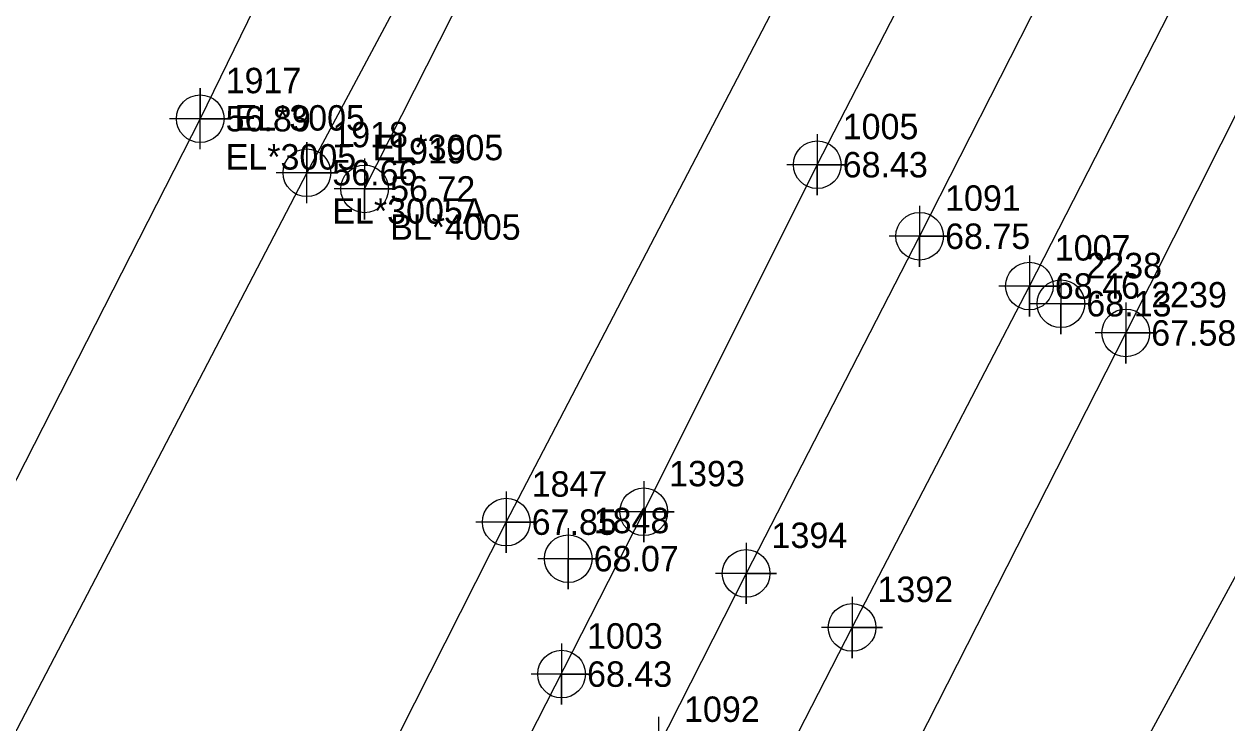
# Model space of a CAD drawing. Extents: x 2062781 to 2066835, y 358981 to 366501.
# Drawn here: x 2065834.6 to 2065952.8, y 365055.9 to 365124.6 of the extents above; entities that cross this region are included whole.
import ezdxf

# ---------------------------------------------------------------- set-up
doc = ezdxf.new("R2010")
doc.units = 0
for name, color, linetype in [('Exist DTM Breakline', 7, 'Continuous'), ('Exist DTM Breakline Cogo Comment', 7, 'Continuous'), ('Exist DTM Breakline Cogo Elevation', 7, 'Continuous'), ('Exist DTM Breakline Cogo Number', 7, 'Continuous'), ('Exist DTM Breakline Cogo Point CELL', 7, 'Continuous'), ('Exist DTM Crownline', 7, 'Continuous'), ('Exist DTM Crownline Cogo Elevation', 7, 'Continuous'), ('Exist DTM Crownline Cogo Number', 7, 'Continuous'), ('Exist DTM Crownline Cogo Point CELL', 7, 'Continuous'), ('Exist DTM Regular Point CELL', 7, 'Continuous'), ('Exist DTM Regular Point Cogo Elevation', 7, 'Continuous'), ('Exist DTM Regular Point Cogo Number', 7, 'Continuous'), ('Exist Roads EOP', 7, 'Continuous'), ('Exist Roads EOP Cogo Elevation', 7, 'Continuous'), ('Exist Roads EOP Cogo Number', 7, 'Continuous'), ('Exist Roads EOP Cogo Point CELL', 7, 'Continuous'), ('Exist Roads Soil', 7, 'Continuous'), ('Exist Roads Soil Cogo Comment', 7, 'Continuous'), ('Exist Roads Soil Cogo Elevation', 7, 'Continuous'), ('Exist Roads Soil Cogo Number', 7, 'Continuous'), ('Exist Roads Soil Cogo Point CELL', 7, 'Continuous')]:
    doc.layers.add(name, color=color, linetype=linetype)

msp = doc.modelspace()

# ---------------------------------------------------------------- linework, layer by layer
at = {"layer": 'Exist DTM Breakline'}
for points in [[(2066391.6, 365972.89), (2066361.73, 365914.52), (2066331.12, 365854.95), (2066302.46, 365802.64), (2066279.52, 365756.79), (2066256.07, 365710.47), (2066233.12, 365662.29), (2066208.82, 365616.84), (2066185.2, 365570.46), (2066159.54, 365522.1), (2066137.86, 365478.97), (2066113.47, 365429.54), (2066089.97, 365381.51), (2066063.32, 365330.49), (2066038.93, 365282.51), (2066014.92, 365234.83), (2065991.3, 365189.77), (2065966.18, 365140.63), (2065942.83, 365094.21), (2065917.49, 365044.37), (2065894.71, 364999.83)], [(2065868.05, 365108.36), (2065887.64, 365147.12), (2065915.95, 365200.53), (2065942.89, 365253.9), (2065967.73, 365303.79), (2065993.42, 365356.29), (2066016.32, 365400.12), (2066036.88, 365439.43), (2066041.92, 365447.71), (2066050.86, 365465.06), (2066067.24, 365500.86), (2066099.12, 365559.9), (2066123.36, 365605.47), (2066146.63, 365650.17), (2066168.17, 365694.53), (2066191.6, 365739.7), (2066213.66, 365782.56), (2066222.79, 365799.42), (2066244.31, 365840.96), (2066263.98, 365879.71), (2066274.73, 365899.77), (2066289.91, 365926.14)], [(2065855.04, 365022.37), (2065881.96, 365075.62), (2065912.8, 365134.88), (2065934.54, 365180.29), (2065958.76, 365228.22), (2065982.22, 365275.67), (2066005.39, 365319.97), (2066028.56, 365365.33), (2066047.41, 365403.57), (2066072.23, 365451.4), (2066094.41, 365496.9), (2066117.74, 365542.01), (2066140.9, 365588.6), (2066164.03, 365634.27), (2066187.25, 365680.45), (2066209.45, 365725.39), (2066232.88, 365773.48), (2066256.9, 365819.9), (2066281.9, 365870.6), (2066303.63, 365917.65)], [(2065937.67, 365040.95), (2065963.89, 365089.22), (2065967.82, 365110.56)]]:
    msp.add_lwpolyline(points, dxfattribs=at)
at = {"layer": 'Exist DTM Breakline Cogo Point CELL'}
for points in [[(2065868.05, 365111.36), (2065868.05, 365105.36), (2065868.05, 365108.36), (2065871.05, 365108.36), (2065865.05, 365108.36)], [(2065942.83, 365097.21), (2065942.83, 365091.21), (2065942.83, 365094.21), (2065945.83, 365094.21), (2065939.83, 365094.21)], [(2065881.96, 365078.62), (2065881.96, 365072.62), (2065881.96, 365075.62), (2065884.96, 365075.62), (2065878.96, 365075.62)]]:
    msp.add_lwpolyline(points, dxfattribs=at)
for centre in [(2065868.05, 365108.36), (2065942.83, 365094.21), (2065881.96, 365075.62)]:
    msp.add_circle(centre, 2.34, dxfattribs=at)
at = {"layer": 'Exist DTM Crownline'}
for points in [[(2066259.93, 365768.45), (2066236.46, 365721.83), (2066212.74, 365674.94), (2066188.43, 365627.04), (2066165.89, 365582.58), (2066140.87, 365533.44), (2066118.2, 365488.77), (2066092.94, 365439.19), (2066070.01, 365393.95), (2066043.74, 365342.11), (2066018.93, 365293.26), (2065993.67, 365243.42), (2065971.81, 365200.42), (2065946.33, 365150.52), (2065922.58, 365103.71), (2065905.53, 365070.58)], [(2065905.53, 365070.58), (2065885.85, 365031.79), (2065868.56, 364997.9), (2065849.54, 364960.7), (2065829.64, 364921.35), (2065809.58, 364881.91), (2065791.06, 364845.43)]]:
    msp.add_lwpolyline(points, dxfattribs=at)
at = {"layer": 'Exist DTM Crownline Cogo Point CELL'}
for points in [[(2065922.58, 365106.71), (2065922.58, 365100.71), (2065922.58, 365103.71), (2065925.58, 365103.71), (2065919.58, 365103.71)], [(2065905.53, 365073.58), (2065905.53, 365067.58), (2065905.53, 365070.58), (2065908.53, 365070.58), (2065902.53, 365070.58)], [(2065905.53, 365073.58), (2065905.53, 365067.58), (2065905.53, 365070.58), (2065908.53, 365070.58), (2065902.53, 365070.58)], [(2065905.53, 365073.58), (2065905.53, 365067.58), (2065905.53, 365070.58), (2065908.53, 365070.58), (2065902.53, 365070.58)], [(2065896.93, 365056.49), (2065896.93, 365050.49), (2065896.93, 365053.49), (2065899.93, 365053.49), (2065893.93, 365053.49)]]:
    msp.add_lwpolyline(points, dxfattribs=at)
for centre in [(2065922.58, 365103.71), (2065905.53, 365070.58), (2065905.53, 365070.58), (2065905.53, 365070.58)]:
    msp.add_circle(centre, 2.34, dxfattribs=at)
at = {"layer": 'Exist DTM Regular Point CELL'}
for points in [[(2065936.46, 365100.08), (2065936.46, 365094.08), (2065936.46, 365097.08), (2065939.46, 365097.08), (2065933.46, 365097.08)], [(2065888.05, 365075.03), (2065888.05, 365069.03), (2065888.05, 365072.03), (2065891.05, 365072.03), (2065885.05, 365072.03)]]:
    msp.add_lwpolyline(points, dxfattribs=at)
for centre in [(2065936.46, 365097.08), (2065888.05, 365072.03)]:
    msp.add_circle(centre, 2.34, dxfattribs=at)
at = {"layer": 'Exist Roads EOP'}
for points in [[(2065915.94, 365065.27), (2065933.36, 365098.82), (2065957.17, 365145.38), (2065982.11, 365194.68), (2066005.18, 365239.69), (2066029.75, 365288.41), (2066054.66, 365336.82), (2066080.34, 365387.56), (2066104, 365434.1), (2066129.47, 365484.53), (2066151.41, 365527.78), (2066176.77, 365577.49), (2066199.44, 365622.47), (2066223.79, 365669.83), (2066246.86, 365715.63), (2066270.89, 365762.9), (2066293.82, 365807.95), (2066320.12, 365859.56), (2066343.32, 365905.56), (2066367.61, 365952.85), (2066390.17, 365997), (2066402.7, 366021.61)], [(2065895.47, 365076.64), (2065912.52, 365110.74), (2065936.33, 365156.98), (2065961.28, 365206.57), (2065984.24, 365251.56), (2066009, 365300.19), (2066033.36, 365348.17), (2066059.15, 365398.75), (2066083.24, 365446.44), (2066108.75, 365496.71), (2066129.9, 365538.17), (2066155.81, 365588.96), (2066178.82, 365634.51), (2066203.21, 365682.83), (2066225.78, 365727.06), (2066250.38, 365775.43)], [(2065779.28, 364851.09), (2065784.35, 364857.33), (2065800.59, 364889.52), (2065820.01, 364928.8), (2065839.55, 364966.5), (2065857.8, 365003.14), (2065875.42, 365037.29), (2065895.47, 365076.64)], [(2065800.45, 364839.68), (2065820.38, 364878.76), (2065840.54, 364917.52), (2065859.89, 364956.08), (2065878.6, 364992.53), (2065896.11, 365026.57), (2065915.94, 365065.27)]]:
    msp.add_lwpolyline(points, dxfattribs=at)
at = {"layer": 'Exist Roads EOP Cogo Point CELL'}
for points in [[(2065912.52, 365113.74), (2065912.52, 365107.74), (2065912.52, 365110.74), (2065915.52, 365110.74), (2065909.52, 365110.74)], [(2065933.36, 365101.82), (2065933.36, 365095.82), (2065933.36, 365098.82), (2065936.36, 365098.82), (2065930.36, 365098.82)], [(2065895.47, 365079.64), (2065895.47, 365073.64), (2065895.47, 365076.64), (2065898.47, 365076.64), (2065892.47, 365076.64)], [(2065895.47, 365079.64), (2065895.47, 365073.64), (2065895.47, 365076.64), (2065898.47, 365076.64), (2065892.47, 365076.64)], [(2065895.47, 365079.64), (2065895.47, 365073.64), (2065895.47, 365076.64), (2065898.47, 365076.64), (2065892.47, 365076.64)], [(2065915.94, 365068.27), (2065915.94, 365062.27), (2065915.94, 365065.27), (2065918.94, 365065.27), (2065912.94, 365065.27)], [(2065915.94, 365068.27), (2065915.94, 365062.27), (2065915.94, 365065.27), (2065918.94, 365065.27), (2065912.94, 365065.27)], [(2065915.94, 365068.27), (2065915.94, 365062.27), (2065915.94, 365065.27), (2065918.94, 365065.27), (2065912.94, 365065.27)], [(2065887.4, 365063.69), (2065887.4, 365057.69), (2065887.4, 365060.69), (2065890.4, 365060.69), (2065884.4, 365060.69)]]:
    msp.add_lwpolyline(points, dxfattribs=at)
for centre in [(2065912.52, 365110.74), (2065933.36, 365098.82), (2065895.47, 365076.64), (2065895.47, 365076.64), (2065895.47, 365076.64), (2065915.94, 365065.27), (2065915.94, 365065.27), (2065915.94, 365065.27), (2065887.4, 365060.69)]:
    msp.add_circle(centre, 2.34, dxfattribs=at)
at = {"layer": 'Exist Roads Soil'}
for points in [[(2066215.29, 365839.32), (2066193.73, 365794.71), (2066173.36, 365754.82), (2066151.9, 365712.15), (2066128.57, 365664.45), (2066106.14, 365619.43), (2066081.59, 365572.67), (2066059.21, 365527.79), (2066035.08, 365482.93), (2066013.05, 365439.11), (2065990.46, 365394.28), (2065968.89, 365350.32), (2065945.11, 365301.86), (2065924.05, 365258.93), (2065901.5, 365213.37), (2065875.73, 365164.13), (2065851.89, 365115.26)], [(2066231.09, 365831.39), (2066206.91, 365786.4), (2066187.29, 365747.66), (2066165.8, 365703.86), (2066142.43, 365657.92), (2066118.99, 365612.17), (2066093.77, 365564.44), (2066069.85, 365517.38), (2066046.67, 365471.42), (2066025.7, 365431.16), (2066001.37, 365382.58), (2065980.65, 365340.33), (2065956.3, 365292.54), (2065935.55, 365249.64), (2065912.26, 365204.19), (2065886.05, 365154.3), (2065862.37, 365109.95)], [(2065851.89, 365115.26), (2065768.54, 364951.8)], [(2065862.37, 365109.95), (2065777.28, 364946.67)]]:
    msp.add_lwpolyline(points, dxfattribs=at)
at = {"layer": 'Exist Roads Soil Cogo Point CELL'}
for points in [[(2065851.89, 365112.26), (2065851.89, 365118.26), (2065851.89, 365115.26), (2065854.89, 365115.26), (2065848.89, 365115.26)], [(2065862.37, 365106.95), (2065862.37, 365112.95), (2065862.37, 365109.95), (2065865.37, 365109.95), (2065859.37, 365109.95)]]:
    msp.add_lwpolyline(points, dxfattribs=at)
for centre in [(2065851.89, 365115.26), (2065862.37, 365109.95)]:
    msp.add_circle(centre, 2.34, dxfattribs=at)

# ---------------------------------------------------------------- texts
at = {"layer": 'Exist DTM Breakline Cogo Comment'}
msp.add_text('BL*4005', height=2.5, dxfattribs=at).set_placement((2065870.55, 365103.36))
at = {"layer": 'Exist DTM Breakline Cogo Elevation'}
for s, p in [('56.72', (2065870.55, 365107.11)), ('67.58', (2065945.33, 365092.96)), ('67.85', (2065884.46, 365074.37))]:
    msp.add_text(s, height=2.5, dxfattribs=at).set_placement(p)
at = {"layer": 'Exist DTM Breakline Cogo Number'}
for s, p in [('1919', (2065870.55, 365110.86)), ('2239', (2065945.33, 365096.71)), ('1847', (2065884.46, 365078.12))]:
    msp.add_text(s, height=2.5, dxfattribs=at).set_placement(p)
at = {"layer": 'Exist DTM Crownline Cogo Elevation'}
msp.add_text('68.75', height=2.5, dxfattribs=at).set_placement((2065925.08, 365102.46))
at = {"layer": 'Exist DTM Crownline Cogo Number'}
for s, p in [('1091', (2065925.08, 365106.21)), ('1394', (2065908.03, 365073.08)), ('1394', (2065908.03, 365073.08)), ('1394', (2065908.03, 365073.08)), ('1092', (2065899.43, 365055.99))]:
    msp.add_text(s, height=2.5, dxfattribs=at).set_placement(p)
at = {"layer": 'Exist DTM Regular Point Cogo Elevation'}
for s, p in [('68.13', (2065938.96, 365095.83)), ('68.07', (2065890.55, 365070.78))]:
    msp.add_text(s, height=2.5, dxfattribs=at).set_placement(p)
at = {"layer": 'Exist DTM Regular Point Cogo Number'}
for s, p in [('2238', (2065938.96, 365099.58)), ('1848', (2065890.55, 365074.53))]:
    msp.add_text(s, height=2.5, dxfattribs=at).set_placement(p)
at = {"layer": 'Exist Roads EOP Cogo Elevation'}
for s, p in [('68.43', (2065915.02, 365109.49)), ('68.46', (2065935.86, 365097.57)), ('68.43', (2065889.9, 365059.44))]:
    msp.add_text(s, height=2.5, dxfattribs=at).set_placement(p)
at = {"layer": 'Exist Roads EOP Cogo Number'}
for s, p in [('1005', (2065915.02, 365113.24)), ('1007', (2065935.86, 365101.32)), ('1393', (2065897.97, 365079.14)), ('1393', (2065897.97, 365079.14)), ('1393', (2065897.97, 365079.14)), ('1392', (2065918.44, 365067.77)), ('1392', (2065918.44, 365067.77)), ('1392', (2065918.44, 365067.77)), ('1003', (2065889.9, 365063.19))]:
    msp.add_text(s, height=2.5, dxfattribs=at).set_placement(p)
at = {"layer": 'Exist Roads Soil Cogo Comment'}
for s, p in [('EL*3005', (2065855.25, 365114.09)), ('EL*3005', (2065868.84, 365111.18)), ('EL*3005', (2065854.39, 365110.26)), ('EL*3005A', (2065864.87, 365104.95))]:
    msp.add_text(s, height=2.5, dxfattribs=at).set_placement(p)
at = {"layer": 'Exist Roads Soil Cogo Elevation'}
for s, p in [('56.89', (2065854.39, 365114.01)), ('56.66', (2065864.87, 365108.7))]:
    msp.add_text(s, height=2.5, dxfattribs=at).set_placement(p)
at = {"layer": 'Exist Roads Soil Cogo Number'}
for s, p in [('1917', (2065854.39, 365117.76)), ('1918', (2065864.87, 365112.45))]:
    msp.add_text(s, height=2.5, dxfattribs=at).set_placement(p)

doc.saveas('drawing.dxf')
